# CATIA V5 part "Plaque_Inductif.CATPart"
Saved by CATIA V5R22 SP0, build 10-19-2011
Part number: Plaque_Inductif
Bounding box of the stored display mesh (mm): x 0 to 5, y -42.4 to 42.4, z -21 to 21
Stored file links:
  U:\S9A\PER\CAO\Assemblage\Cadre\Chariot_Y\Prehenseur\Plaque_Inductif.CATPart
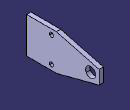
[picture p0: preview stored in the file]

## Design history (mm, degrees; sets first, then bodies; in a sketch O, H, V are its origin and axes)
Body1 (main body)
  Sketch1 on yz-plane, origin (0, 0, 0), H (0, 1, 0), V (0, 0, 1)
    line L1 (-42.4, 21) -> (42.4, 21)
    line L2 (42.4, 21) -> (42.4, -21)
    line L3 (42.4, -21) -> (-42.4, -21)
    line L4 (-42.4, -21) -> (-42.4, 21)
    distance L1 L3 = 42
    distance L2 L4 = 84.8
    horizontal: L1 H, L3 H
    vertical: L2 V, L4 V
    symmetry: L1 L3 H, L2 L4 V
  Pad1: profile Sketch1, direction (1, 0, 0), length 5
  Sketch2 on yz-plane, origin (0, 0, 0), H (0, 1, 0), V (0, 0, 1)
    point P1 (-13.4, 15)
    point P2 (-13.4, -15)
    point P3 (32.4, 0)
    reference projected line E1 (42.4, -21) -> (42.4, 21) from edge [face of Pad1 from Sketch1.L2 | end face of Pad1]
    reference projected line E2 (42.4, -21) -> (42.4, 21) from edge [face of Pad1 from Sketch1.L2 | end face of Pad1]
    distance P1 E1 = 55.8
    distance P1 P2 = 30
    distance P3 E2 = 10
    coincidence: P3 H
    symmetry: P2 P1 H
  Sketch3 on start face of Pad1, origin (0, 20.9, 0), H (0, 1, 0), V (0, 0, -1)
    point P1 (11.5, 0)
    reference projected point E1 (11.5, 0) from Sketch2.P3
    coincidence: E1 P1
  Hole1: placed by Sketch3, at (0, 32.4, 0) direction (1, 0, 0), diameter 12, depth 10
  Sketch4 on start face of Pad1, origin (0, -24.9, 15), H (0, 1, 0), V (0, 0, -1)
    point P1 (11.5, 0)
    reference projected point E1 (11.5, 0) from Sketch2.P1
    coincidence: E1 P1
  Hole2: placed by Sketch4, at (0, -13.4, 15) direction (1, 0, 0), diameter 5, depth 10
  Mirror1: of Hole2, about xy-plane
  Chamfer1: length 50, second length 13, on edge [face of Pad1 from Sketch1.L1 | face of Pad1 from Sketch1.L2]; edge [face of Pad1 from Sketch1.L2 | face of Pad1 from Sketch1.L3]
